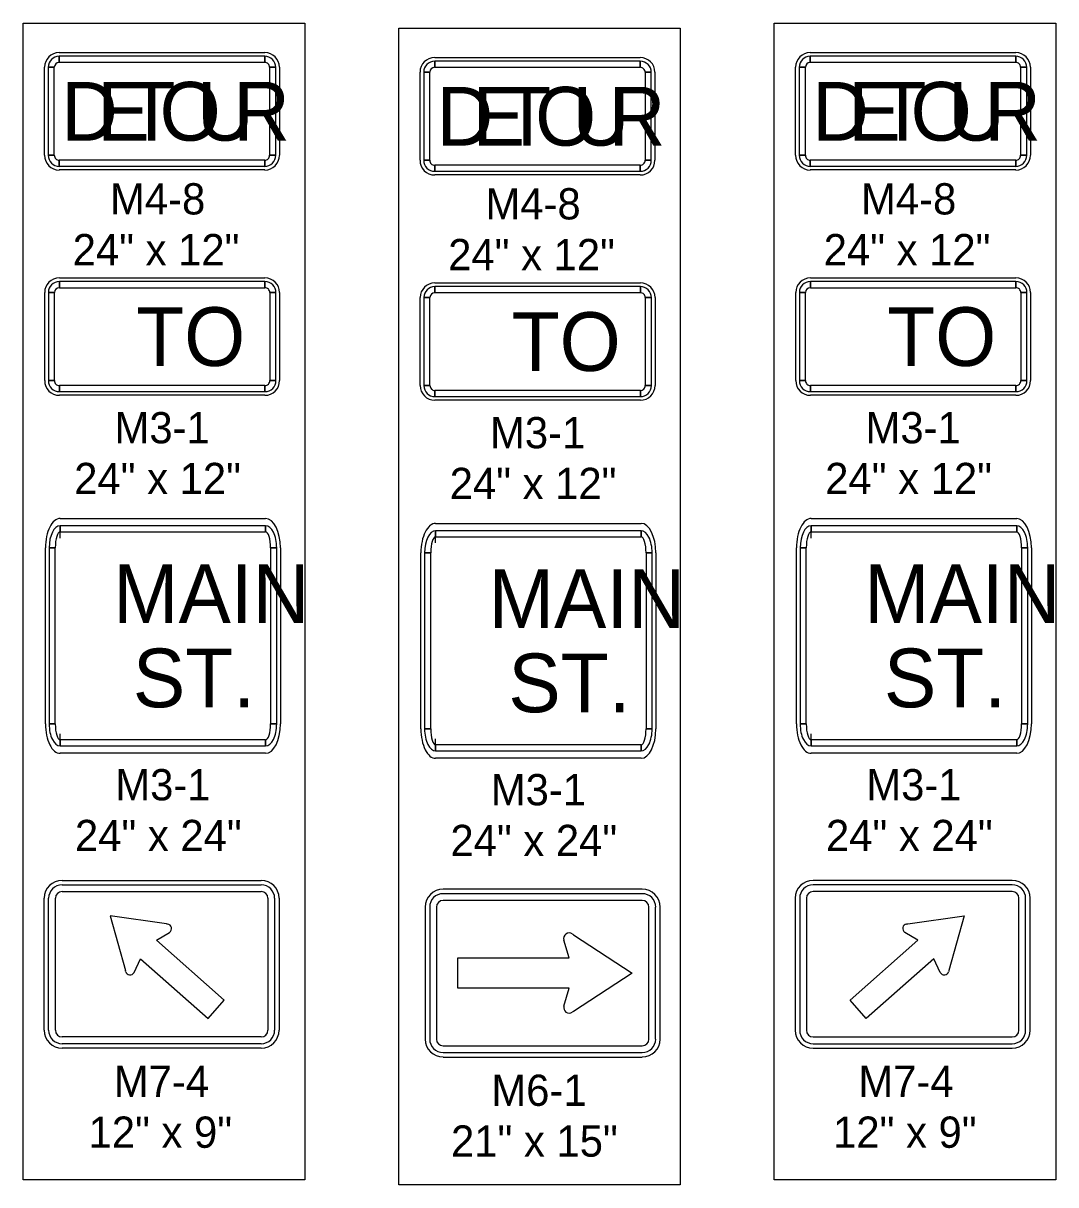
# Model space of a CAD drawing. Extents: x 10133 to 81668, y 6132 to 11018.
# Drawn here: x 12333 to 12597.3, y 6725.2 to 7022.5 of the extents above; entities that cross this region are included whole.
import ezdxf

# ---------------------------------------------------------------- set-up
doc = ezdxf.new("R2010")
doc.units = 0
for name, color, linetype in [('dsnTextFinalPlan', 7, 'Continuous'), ('Level 10', 7, 'Continuous'), ('Level 5', 7, 'Continuous')]:
    doc.layers.add(name, color=color, linetype=linetype)

msp = doc.modelspace()

# ---------------------------------------------------------------- linework, layer by layer
at = {"layer": 'dsnTextFinalPlan'}
for p, q in [((12342.93, 6803.11), (12393.89, 6803.11)), ((12586.15, 6803.11), (12535.18, 6803.11)), ((12338.35, 6764.74), (12338.35, 6798.53)), ((12398.48, 6798.53), (12398.48, 6764.74)), ((12530.6, 6798.53), (12530.6, 6764.74)), ((12590.73, 6764.74), (12590.73, 6798.53)), ((12393.89, 6760.16), (12342.93, 6760.16)), ((12535.18, 6760.16), (12586.15, 6760.16))]:
    msp.add_line(p, q, dxfattribs=at)
for points in [[(12332.98, 7022.55), (12405.05, 7022.55), (12405.05, 6726.45), (12332.98, 6726.45)], [(12429.1, 7021.28), (12501.16, 7021.28), (12501.16, 6725.18), (12429.1, 6725.18)], [(12525.23, 7022.55), (12597.3, 7022.55), (12597.3, 6726.45), (12525.23, 6726.45)]]:
    msp.add_lwpolyline(points, close=True, dxfattribs=at)
for points in [[(12369.63, 6791.97), (12355.26, 6794.04), (12359.12, 6780.06)], [(12559.44, 6791.97), (12573.81, 6794.04), (12569.95, 6780.06)], [(12361.34, 6779.55), (12362.96, 6783.06), (12380.29, 6767.77), (12384.44, 6772.48), (12367.12, 6787.77), (12370.41, 6789.8)], [(12567.74, 6779.55), (12566.11, 6783.06), (12548.79, 6767.77), (12544.63, 6772.48), (12561.96, 6787.77), (12558.66, 6789.8)]]:
    msp.add_lwpolyline(points, dxfattribs=at)
for centre, radius, start, end in [((12342.93, 6798.53), 4.58, 90, 180), ((12393.89, 6798.53), 4.58, 0, 90), ((12535.18, 6798.53), 4.58, 90, 180), ((12586.15, 6798.53), 4.58, 360, 90), ((12386.16, 6906.75), 115.96, 261.8049, 261.9654), ((12369.79, 6790.78), 1.16, 302.6073, 81.9654), ((12559.28, 6790.78), 1.16, 98.0346, 237.3927), ((12542.91, 6906.75), 115.96, 278.0346, 278.1951), ((12247.34, 6749.2), 115.96, 15.2659, 15.4333), ((12681.73, 6749.2), 115.96, 164.5667, 164.7341), ((12360.31, 6780.03), 1.14, 195.2659, 334.5454), ((12568.76, 6780.03), 1.14, 205.4546, 344.7341), ((12342.93, 6764.74), 4.58, 180, 270), ((12393.89, 6764.74), 4.58, 270, 0), ((12535.18, 6764.74), 4.58, 180, 270), ((12586.15, 6764.74), 4.58, 270, 0)]:
    msp.add_arc(centre, radius, start, end, dxfattribs=at)
at = {"layer": 'Level 10'}
for p, q in [((12342.19, 7015.04), (12394.8, 7015.04)), ((12534.44, 7015.04), (12587.05, 7015.04)), ((12342.19, 7012.54), (12342.19, 7014.1)), ((12394.8, 7014.1), (12394.8, 7012.54)), ((12438.31, 7013.77), (12490.92, 7013.77)), ((12438.31, 7011.26), (12438.31, 7012.83)), ((12490.92, 7012.83), (12490.92, 7011.26)), ((12534.44, 7012.54), (12534.44, 7014.1)), ((12587.05, 7014.1), (12587.05, 7012.54)), ((12338.43, 6988.73), (12338.43, 7011.28)), ((12339.37, 7011.28), (12340.94, 7011.28)), ((12396.05, 7011.28), (12397.62, 7011.28)), ((12398.56, 7011.28), (12398.56, 6988.73)), ((12434.55, 6987.46), (12434.55, 7010.01)), ((12435.49, 7010.01), (12437.05, 7010.01)), ((12492.17, 7010.01), (12493.74, 7010.01)), ((12494.68, 7010.01), (12494.68, 6987.46)), ((12530.68, 6988.73), (12530.68, 7011.28)), ((12531.62, 7011.28), (12533.19, 7011.28)), ((12588.3, 7011.28), (12589.87, 7011.28)), ((12590.81, 7011.28), (12590.81, 6988.73)), ((12340.94, 6988.73), (12339.37, 6988.73)), ((12397.62, 6988.73), (12396.05, 6988.73)), ((12533.19, 6988.73), (12531.62, 6988.73)), ((12589.87, 6988.73), (12588.3, 6988.73)), ((12342.19, 6985.92), (12342.19, 6987.48)), ((12394.8, 6987.48), (12394.8, 6985.92)), ((12437.05, 6987.46), (12435.49, 6987.46)), ((12438.31, 6984.64), (12438.31, 6986.21)), ((12490.92, 6986.21), (12490.92, 6984.64)), ((12493.74, 6987.46), (12492.17, 6987.46)), ((12534.44, 6985.92), (12534.44, 6987.48)), ((12587.05, 6987.48), (12587.05, 6985.92)), ((12394.8, 6984.98), (12342.19, 6984.98)), ((12490.92, 6983.7), (12438.31, 6983.7)), ((12587.05, 6984.98), (12534.44, 6984.98)), ((12342.23, 6957.35), (12394.85, 6957.35)), ((12342.23, 6954.85), (12342.23, 6956.41)), ((12394.85, 6956.41), (12394.85, 6954.85)), ((12438.35, 6956.08), (12490.96, 6956.08)), ((12534.49, 6957.35), (12587.1, 6957.35)), ((12534.49, 6954.85), (12534.49, 6956.41)), ((12587.1, 6956.41), (12587.1, 6954.85)), ((12338.48, 6931.05), (12338.48, 6953.6)), ((12339.42, 6953.6), (12340.98, 6953.6)), ((12396.1, 6953.6), (12397.67, 6953.6)), ((12398.61, 6953.6), (12398.61, 6931.05)), ((12438.35, 6953.58), (12438.35, 6955.14)), ((12490.96, 6955.14), (12490.96, 6953.58)), ((12530.73, 6931.05), (12530.73, 6953.6)), ((12531.67, 6953.6), (12533.23, 6953.6)), ((12588.35, 6953.6), (12589.92, 6953.6)), ((12590.86, 6953.6), (12590.86, 6931.05)), ((12434.59, 6929.78), (12434.59, 6952.32)), ((12435.53, 6952.32), (12437.1, 6952.32)), ((12492.22, 6952.32), (12493.78, 6952.32)), ((12494.72, 6952.32), (12494.72, 6929.78)), ((12340.98, 6931.05), (12339.42, 6931.05)), ((12342.23, 6928.23), (12342.23, 6929.8)), ((12394.85, 6929.8), (12394.85, 6928.23)), ((12397.67, 6931.05), (12396.1, 6931.05)), ((12437.1, 6929.78), (12435.53, 6929.78)), ((12493.78, 6929.78), (12492.22, 6929.78)), ((12533.23, 6931.05), (12531.67, 6931.05)), ((12534.49, 6928.23), (12534.49, 6929.8)), ((12587.1, 6929.8), (12587.1, 6928.23)), ((12589.92, 6931.05), (12588.35, 6931.05)), ((12394.85, 6927.29), (12342.23, 6927.29)), ((12438.35, 6926.96), (12438.35, 6928.52)), ((12490.96, 6926.02), (12438.35, 6926.02)), ((12490.96, 6928.52), (12490.96, 6926.96)), ((12587.1, 6927.29), (12534.49, 6927.29)), ((12342.43, 6895.77), (12395.04, 6895.77)), ((12342.43, 6890.76), (12342.43, 6893.89)), ((12395.04, 6893.89), (12395.04, 6892.33)), ((12438.54, 6894.5), (12491.16, 6894.5)), ((12534.68, 6895.77), (12587.29, 6895.77)), ((12534.68, 6890.76), (12534.68, 6893.89)), ((12587.29, 6893.89), (12587.29, 6892.33)), ((12438.54, 6889.49), (12438.54, 6892.62)), ((12491.16, 6892.62), (12491.16, 6891.05)), ((12338.67, 6843.16), (12338.67, 6888.25)), ((12339.61, 6888.25), (12341.17, 6888.25)), ((12396.29, 6888.25), (12397.86, 6888.25)), ((12398.8, 6888.25), (12398.8, 6843.16)), ((12530.92, 6843.16), (12530.92, 6888.25)), ((12531.86, 6888.25), (12533.42, 6888.25)), ((12588.54, 6888.25), (12590.11, 6888.25)), ((12591.05, 6888.25), (12591.05, 6843.16)), ((12434.78, 6841.89), (12434.78, 6886.98)), ((12435.72, 6886.98), (12437.29, 6886.98)), ((12492.41, 6886.98), (12493.97, 6886.98)), ((12494.91, 6886.98), (12494.91, 6841.89)), ((12341.17, 6843.16), (12339.61, 6843.16)), ((12397.86, 6843.16), (12396.29, 6843.16)), ((12533.42, 6843.16), (12531.86, 6843.16)), ((12590.11, 6843.16), (12588.54, 6843.16)), ((12342.43, 6837.52), (12342.43, 6840.65)), ((12437.29, 6841.89), (12435.72, 6841.89)), ((12493.97, 6841.89), (12492.41, 6841.89)), ((12534.68, 6837.52), (12534.68, 6840.65)), ((12395.04, 6839.09), (12395.04, 6837.52)), ((12438.54, 6836.25), (12438.54, 6839.38)), ((12491.16, 6837.81), (12491.16, 6836.25)), ((12587.29, 6839.09), (12587.29, 6837.52)), ((12395.04, 6835.64), (12342.43, 6835.64)), ((12491.16, 6834.37), (12438.54, 6834.37)), ((12587.29, 6835.64), (12534.68, 6835.64)), ((12342.93, 6801.96), (12393.89, 6801.96)), ((12491.44, 6800.84), (12440.47, 6800.84)), ((12586.15, 6801.96), (12535.18, 6801.96)), ((12339.49, 6764.74), (12339.49, 6798.53)), ((12341.21, 6764.74), (12341.21, 6798.53)), ((12342.93, 6800.24), (12393.89, 6800.24)), ((12395.61, 6798.53), (12395.61, 6764.74)), ((12397.33, 6798.53), (12397.33, 6764.74)), ((12491.44, 6799.7), (12440.47, 6799.7)), ((12491.44, 6797.98), (12440.47, 6797.98)), ((12531.74, 6798.53), (12531.74, 6764.74)), ((12533.46, 6798.53), (12533.46, 6764.74)), ((12586.15, 6800.24), (12535.18, 6800.24)), ((12587.86, 6764.74), (12587.86, 6798.53)), ((12589.58, 6764.74), (12589.58, 6798.53)), ((12435.89, 6796.26), (12435.89, 6762.48)), ((12437.03, 6796.26), (12437.03, 6762.48)), ((12438.75, 6796.26), (12438.75, 6762.48)), ((12493.15, 6762.48), (12493.15, 6796.26)), ((12494.87, 6762.48), (12494.87, 6796.26)), ((12496.02, 6762.48), (12496.02, 6796.26)), ((12393.89, 6763.02), (12342.93, 6763.02)), ((12535.18, 6763.02), (12586.15, 6763.02)), ((12393.89, 6761.3), (12342.93, 6761.3)), ((12440.47, 6760.76), (12491.44, 6760.76)), ((12535.18, 6761.3), (12586.15, 6761.3)), ((12440.47, 6759.04), (12491.44, 6759.04)), ((12440.47, 6757.89), (12491.44, 6757.89))]:
    msp.add_line(p, q, dxfattribs=at)
for points in [[(12394.8, 7014.1), (12342.19, 7014.1), (12342.19, 7012.54), (12394.8, 7012.54), (12394.8, 7014.1)], [(12490.92, 7012.83), (12438.31, 7012.83), (12438.31, 7011.26), (12490.92, 7011.26), (12490.92, 7012.83)], [(12587.05, 7014.1), (12534.44, 7014.1), (12534.44, 7012.54), (12587.05, 7012.54), (12587.05, 7014.1)], [(12339.37, 7011.28), (12339.37, 6988.73), (12340.94, 6988.73), (12340.94, 7011.28), (12339.37, 7011.28)], [(12397.62, 6988.73), (12397.62, 7011.28), (12396.05, 7011.28), (12396.05, 6988.73), (12397.62, 6988.73)], [(12435.49, 7010.01), (12435.49, 6987.46), (12437.05, 6987.46), (12437.05, 7010.01), (12435.49, 7010.01)], [(12493.74, 6987.46), (12493.74, 7010.01), (12492.17, 7010.01), (12492.17, 6987.46), (12493.74, 6987.46)], [(12531.62, 7011.28), (12531.62, 6988.73), (12533.19, 6988.73), (12533.19, 7011.28), (12531.62, 7011.28)], [(12589.87, 6988.73), (12589.87, 7011.28), (12588.3, 7011.28), (12588.3, 6988.73), (12589.87, 6988.73)], [(12342.19, 6985.92), (12394.8, 6985.92), (12394.8, 6987.48), (12342.19, 6987.48), (12342.19, 6985.92)], [(12438.31, 6984.64), (12490.92, 6984.64), (12490.92, 6986.21), (12438.31, 6986.21), (12438.31, 6984.64)], [(12534.44, 6985.92), (12587.05, 6985.92), (12587.05, 6987.48), (12534.44, 6987.48), (12534.44, 6985.92)], [(12394.85, 6956.41), (12342.23, 6956.41), (12342.23, 6954.85), (12394.85, 6954.85), (12394.85, 6956.41)], [(12587.1, 6956.41), (12534.49, 6956.41), (12534.49, 6954.85), (12587.1, 6954.85), (12587.1, 6956.41)], [(12339.42, 6953.6), (12339.42, 6931.05), (12340.98, 6931.05), (12340.98, 6953.6), (12339.42, 6953.6)], [(12397.67, 6931.05), (12397.67, 6953.6), (12396.1, 6953.6), (12396.1, 6931.05), (12397.67, 6931.05)], [(12490.96, 6955.14), (12438.35, 6955.14), (12438.35, 6953.58), (12490.96, 6953.58), (12490.96, 6955.14)], [(12531.67, 6953.6), (12531.67, 6931.05), (12533.23, 6931.05), (12533.23, 6953.6), (12531.67, 6953.6)], [(12589.92, 6931.05), (12589.92, 6953.6), (12588.35, 6953.6), (12588.35, 6931.05), (12589.92, 6931.05)], [(12435.53, 6952.32), (12435.53, 6929.78), (12437.1, 6929.78), (12437.1, 6952.32), (12435.53, 6952.32)], [(12493.78, 6929.78), (12493.78, 6952.32), (12492.22, 6952.32), (12492.22, 6929.78), (12493.78, 6929.78)], [(12342.23, 6928.23), (12394.85, 6928.23), (12394.85, 6929.8), (12342.23, 6929.8), (12342.23, 6928.23)], [(12534.49, 6928.23), (12587.1, 6928.23), (12587.1, 6929.8), (12534.49, 6929.8), (12534.49, 6928.23)], [(12438.35, 6926.96), (12490.96, 6926.96), (12490.96, 6928.52), (12438.35, 6928.52), (12438.35, 6926.96)], [(12395.04, 6893.89), (12342.43, 6893.89), (12342.43, 6892.33), (12395.04, 6892.33), (12395.04, 6893.89)], [(12587.29, 6893.89), (12534.68, 6893.89), (12534.68, 6892.33), (12587.29, 6892.33), (12587.29, 6893.89)], [(12491.16, 6892.62), (12438.54, 6892.62), (12438.54, 6891.05), (12491.16, 6891.05), (12491.16, 6892.62)], [(12339.61, 6888.25), (12339.61, 6843.16), (12341.17, 6843.16), (12341.17, 6888.25), (12339.61, 6888.25)], [(12397.86, 6843.16), (12397.86, 6888.25), (12396.29, 6888.25), (12396.29, 6843.16), (12397.86, 6843.16)], [(12531.86, 6888.25), (12531.86, 6843.16), (12533.42, 6843.16), (12533.42, 6888.25), (12531.86, 6888.25)], [(12590.11, 6843.16), (12590.11, 6888.25), (12588.54, 6888.25), (12588.54, 6843.16), (12590.11, 6843.16)], [(12435.72, 6886.98), (12435.72, 6841.89), (12437.29, 6841.89), (12437.29, 6886.98), (12435.72, 6886.98)], [(12493.97, 6841.89), (12493.97, 6886.98), (12492.41, 6886.98), (12492.41, 6841.89), (12493.97, 6841.89)], [(12342.43, 6837.52), (12395.04, 6837.52), (12395.04, 6839.09), (12342.43, 6839.09), (12342.43, 6837.52)], [(12438.54, 6836.25), (12491.16, 6836.25), (12491.16, 6837.81), (12438.54, 6837.81), (12438.54, 6836.25)], [(12534.68, 6837.52), (12587.29, 6837.52), (12587.29, 6839.09), (12534.68, 6839.09), (12534.68, 6837.52)]]:
    msp.add_lwpolyline(points, close=True, dxfattribs=at)
for points in [[(12473.87, 6789.19), (12488.86, 6779.37), (12473.87, 6769.58)], [(12471.4, 6770.91), (12472.77, 6775.49), (12444.24, 6775.49), (12444.24, 6783.25), (12472.77, 6783.25), (12471.37, 6787.82)]]:
    msp.add_lwpolyline(points, dxfattribs=at)
for centre, radius, start, end in [((12342.19, 7011.28), 3.76, 90, 180), ((12394.8, 7011.28), 3.76, 0, 90), ((12534.44, 7011.28), 3.76, 90, 180), ((12587.05, 7011.28), 3.76, 0, 90), ((12342.19, 7011.28), 2.82, 90.0002, 179.9998), ((12342.19, 7011.28), 1.25, 90.0002, 179.9998), ((12394.8, 7011.28), 2.82, 0, 90.0002), ((12394.8, 7011.28), 1.25, 0, 90.0002), ((12438.31, 7010.01), 3.76, 90, 180), ((12438.31, 7010.01), 2.82, 90.0002, 179.9998), ((12490.92, 7010.01), 3.76, 0, 90), ((12490.92, 7010.01), 2.82, 0, 90.0002), ((12534.44, 7011.28), 2.82, 90.0002, 179.9998), ((12534.44, 7011.28), 1.25, 90.0002, 179.9998), ((12587.05, 7011.28), 2.82, 0, 90.0002), ((12587.05, 7011.28), 1.25, 0, 90.0002), ((12438.31, 7010.01), 1.25, 90.0002, 179.9998), ((12490.92, 7010.01), 1.25, 0, 90.0002), ((12342.19, 6988.73), 3.76, 180, 270), ((12342.19, 6988.73), 2.82, 179.9998, 270.0001), ((12342.19, 6988.73), 1.25, 179.9998, 270.0001), ((12394.8, 6988.73), 2.82, 270.0001, 0.0003), ((12394.8, 6988.73), 1.25, 270.0001, 0.0003), ((12394.8, 6988.73), 3.76, 270, 359.9911), ((12534.44, 6988.73), 3.76, 180, 270), ((12534.44, 6988.73), 2.82, 179.9998, 270.0001), ((12534.44, 6988.73), 1.25, 179.9998, 270.0001), ((12587.05, 6988.73), 2.82, 270.0001, 0.0003), ((12587.05, 6988.73), 1.25, 270.0001, 0.0003), ((12587.05, 6988.73), 3.76, 270, 359.9911), ((12438.31, 6987.46), 3.76, 180, 270), ((12438.31, 6987.46), 2.82, 179.9998, 270.0001), ((12438.31, 6987.46), 1.25, 179.9998, 270.0001), ((12490.92, 6987.46), 2.82, 270.0001, 0.0003), ((12490.92, 6987.46), 1.25, 270.0001, 0.0003), ((12490.92, 6987.46), 3.76, 270, 359.9911), ((12342.23, 6953.6), 3.76, 90, 180), ((12342.23, 6953.6), 2.82, 90.0002, 179.9998), ((12394.85, 6953.6), 3.76, 0, 90), ((12394.85, 6953.6), 2.82, 0, 90.0002), ((12438.35, 6952.32), 3.76, 90, 180), ((12490.96, 6952.32), 3.76, 0, 90), ((12534.49, 6953.6), 3.76, 90, 180), ((12534.49, 6953.6), 2.82, 90.0002, 179.9998), ((12587.1, 6953.6), 3.76, 0, 90), ((12587.1, 6953.6), 2.82, 0, 90.0002), ((12342.23, 6953.6), 1.25, 90.0002, 179.9998), ((12394.85, 6953.6), 1.25, 0, 90.0002), ((12438.35, 6952.32), 2.82, 90.0002, 179.9998), ((12438.35, 6952.32), 1.25, 90.0002, 179.9998), ((12490.96, 6952.32), 2.82, 0, 90.0002), ((12490.96, 6952.32), 1.25, 0, 90.0002), ((12534.49, 6953.6), 1.25, 90.0002, 179.9998), ((12587.1, 6953.6), 1.25, 0, 90.0002), ((12342.23, 6931.05), 3.76, 180, 270), ((12342.23, 6931.05), 2.82, 179.9998, 270.0001), ((12342.23, 6931.05), 1.25, 179.9998, 270.0001), ((12394.85, 6931.05), 2.82, 270.0001, 0.0003), ((12394.85, 6931.05), 1.25, 270.0001, 0.0003), ((12394.85, 6931.05), 3.76, 270, 359.9911), ((12438.35, 6929.78), 3.76, 180, 270), ((12438.35, 6929.78), 2.82, 179.9998, 270.0001), ((12438.35, 6929.78), 1.25, 179.9998, 270.0001), ((12490.96, 6929.78), 2.82, 270.0001, 0.0003), ((12490.96, 6929.78), 1.25, 270.0001, 0.0003), ((12490.96, 6929.78), 3.76, 270, 359.9911), ((12534.49, 6931.05), 3.76, 180, 270), ((12534.49, 6931.05), 2.82, 179.9998, 270.0001), ((12534.49, 6931.05), 1.25, 179.9998, 270.0001), ((12587.1, 6931.05), 2.82, 270.0001, 0.0003), ((12587.1, 6931.05), 1.25, 270.0001, 0.0003), ((12587.1, 6931.05), 3.76, 270, 359.9911), ((12342.93, 6798.53), 3.44, 90, 180), ((12393.89, 6798.53), 3.44, 0, 90), ((12440.47, 6796.26), 4.58, 90, 180), ((12491.44, 6796.26), 4.58, 360, 90), ((12535.18, 6798.53), 3.44, 90, 180), ((12586.15, 6798.53), 3.44, 0, 90), ((12342.93, 6798.53), 1.72, 90, 180), ((12393.89, 6798.53), 1.72, 0, 90), ((12440.47, 6796.26), 3.44, 90, 180), ((12440.47, 6796.26), 1.72, 90, 180), ((12491.44, 6796.26), 3.44, 0, 90), ((12491.44, 6796.26), 1.72, 0, 90), ((12535.18, 6798.53), 1.72, 90, 180), ((12586.15, 6798.53), 1.72, 0, 90), ((12472.75, 6788.21), 1.43, 56.6109, 195.9691), ((12552.32, 6908.94), 143.16, 236.6109, 236.7714), ((12472.75, 6770.53), 1.4, 164.0309, 303.3104), ((12552.14, 6649.71), 143.16, 123.143, 123.3104), ((12342.93, 6764.74), 3.44, 180, 270), ((12342.93, 6764.74), 1.72, 180, 270), ((12393.89, 6764.74), 3.44, 270, 0), ((12393.89, 6764.74), 1.72, 270, 0), ((12440.47, 6762.48), 4.58, 180, 270), ((12440.47, 6762.48), 3.44, 180, 270), ((12440.47, 6762.48), 1.72, 180, 270), ((12491.44, 6762.48), 4.58, 270, 0), ((12491.44, 6762.48), 3.44, 270, 360), ((12491.44, 6762.48), 1.72, 270, 0), ((12535.18, 6764.74), 3.44, 180, 270), ((12535.18, 6764.74), 1.72, 180, 270), ((12586.15, 6764.74), 3.44, 270, 360), ((12586.15, 6764.74), 1.72, 270, 0)]:
    msp.add_arc(centre, radius, start, end, dxfattribs=at)
for centre, major_axis, ratio, start_param, end_param in [((12342.43, 6888.25), (0, 7.52), 0.5, 6.283185, 7.853982), ((12342.43, 6888.25), (0, 5.64), 0.5, 0.000004, 1.570794), ((12395.04, 6888.25), (0, 7.52), 0.5, 4.712389, 6.283185), ((12395.04, 6888.25), (0, 5.64), 0.5, 4.712389, 6.283189), ((12438.54, 6886.98), (0, 7.52), 0.5, 6.283185, 7.853982), ((12491.16, 6886.98), (0, 7.52), 0.5, 4.712389, 6.283185), ((12534.68, 6888.25), (0, 7.52), 0.5, 6.283185, 7.853982), ((12534.68, 6888.25), (0, 5.64), 0.5, 0.000004, 1.570794), ((12587.29, 6888.25), (0, 7.52), 0.5, 4.712389, 6.283185), ((12587.29, 6888.25), (0, 5.64), 0.5, 4.712389, 6.283189), ((12342.43, 6888.25), (0, 4.07), 0.307692, 0.000004, 1.570794), ((12395.04, 6888.25), (0, 4.07), 0.307692, 4.712389, 6.283189), ((12438.54, 6886.98), (0, 5.64), 0.5, 0.000004, 1.570794), ((12438.54, 6886.98), (0, 4.07), 0.307692, 0.000004, 1.570794), ((12491.16, 6886.98), (0, 5.64), 0.5, 4.712389, 6.283189), ((12491.16, 6886.98), (0, 4.07), 0.307692, 4.712389, 6.283189), ((12534.68, 6888.25), (0, 4.07), 0.307692, 0.000004, 1.570794), ((12587.29, 6888.25), (0, 4.07), 0.307692, 4.712389, 6.283189), ((12342.43, 6843.16), (0, 7.52), 0.5, 1.570796, 3.141593), ((12342.43, 6843.16), (0, 5.64), 0.5, 1.570794, 3.141594), ((12342.43, 6843.16), (0, 4.07), 0.307692, 1.570794, 3.141594), ((12395.04, 6843.16), (0, 5.64), 0.5, 3.141594, 4.712394), ((12395.04, 6843.16), (0, 4.07), 0.307692, 3.141594, 4.712394), ((12395.04, 6843.16), (0, 7.52), 0.5, 3.141593, 4.712234), ((12534.68, 6843.16), (0, 7.52), 0.5, 1.570796, 3.141593), ((12534.68, 6843.16), (0, 5.64), 0.5, 1.570794, 3.141594), ((12534.68, 6843.16), (0, 4.07), 0.307692, 1.570794, 3.141594), ((12587.29, 6843.16), (0, 5.64), 0.5, 3.141594, 4.712394), ((12587.29, 6843.16), (0, 4.07), 0.307692, 3.141594, 4.712394), ((12587.29, 6843.16), (0, 7.52), 0.5, 3.141593, 4.712234), ((12438.54, 6841.89), (0, 7.52), 0.5, 1.570796, 3.141593), ((12438.54, 6841.89), (0, 5.64), 0.5, 1.570794, 3.141594), ((12438.54, 6841.89), (0, 4.07), 0.307692, 1.570794, 3.141594), ((12491.16, 6841.89), (0, 5.64), 0.5, 3.141594, 4.712394), ((12491.16, 6841.89), (0, 4.07), 0.307692, 3.141594, 4.712394), ((12491.16, 6841.89), (0, 7.52), 0.5, 3.141593, 4.712234)]:
    msp.add_ellipse(centre, major_axis=major_axis, ratio=ratio, start_param=start_param, end_param=end_param, dxfattribs=at)

# ---------------------------------------------------------------- texts
for s, height, p in [('D', 15.03, (12342.67, 6992.49)), ('E', 15.03, (12351.91, 6992.49)), ('T', 15.03, (12359.69, 6992.49)), ('O', 15.03, (12367.9, 6992.49)), ('U', 15.03, (12377.49, 6992.49)), ('R', 15.03, (12386.73, 6992.49)), ('D', 15.03, (12438.79, 6991.22)), ('E', 15.03, (12448.03, 6991.22)), ('T', 15.03, (12455.81, 6991.22)), ('O', 15.03, (12464.02, 6991.22)), ('U', 15.03, (12473.61, 6991.22)), ('R', 15.03, (12482.85, 6991.22)), ('D', 15.03, (12534.93, 6992.49)), ('E', 15.03, (12544.16, 6992.49)), ('T', 15.03, (12551.94, 6992.49)), ('O', 15.03, (12560.15, 6992.49)), ('U', 15.03, (12569.74, 6992.49)), ('R', 15.03, (12578.98, 6992.49)), ('TO', 15.032, (12361.9, 6934.81)), ('TO', 15.032, (12554.15, 6934.81)), ('TO', 15.032, (12458.02, 6933.53)), ('MAIN', 15.032, (12355.99, 6868.96)), ('MAIN', 15.032, (12452.11, 6867.68)), ('MAIN', 15.032, (12548.24, 6868.96)), ('ST.', 15.032, (12361.04, 6847.42)), ('ST.', 15.032, (12457.16, 6846.15)), ('ST.', 15.032, (12553.3, 6847.42))]:
    msp.add_text(s, height=height, dxfattribs=at).set_placement(p)
at = {"layer": 'Level 5'}
for s, p in [('M4-8', (12355.2, 6973.59)), ('M4-8', (12451.31, 6972.32)), ('M4-8', (12547.45, 6973.59)), ('24" x 12"', (12345.64, 6960.59)), ('24" x 12"', (12441.76, 6959.32)), ('24" x 12"', (12537.89, 6960.59)), ('M3-1', (12356.36, 6915)), ('M3-1', (12548.61, 6915)), ('M3-1', (12452.48, 6913.73)), ('24" x 12"', (12346.03, 6902)), ('24" x 12"', (12442.15, 6900.73)), ('24" x 12"', (12538.28, 6902)), ('M3-1', (12356.55, 6823.6)), ('M3-1', (12548.8, 6823.6)), ('M3-1', (12452.67, 6822.33)), ('24" x 24"', (12346.22, 6810.6)), ('24" x 24"', (12538.47, 6810.6)), ('24" x 24"', (12442.34, 6809.33)), ('M7-4', (12356.18, 6747.65)), ('M6-1', (12452.82, 6745.38)), ('M7-4', (12546.77, 6747.65)), ('12" x 9"', (12349.71, 6734.65)), ('12" x 9"', (12540.3, 6734.65)), ('21" x 15"', (12442.49, 6732.38))]:
    msp.add_text(s, height=8, dxfattribs=at).set_placement(p)

doc.saveas('drawing.dxf')
